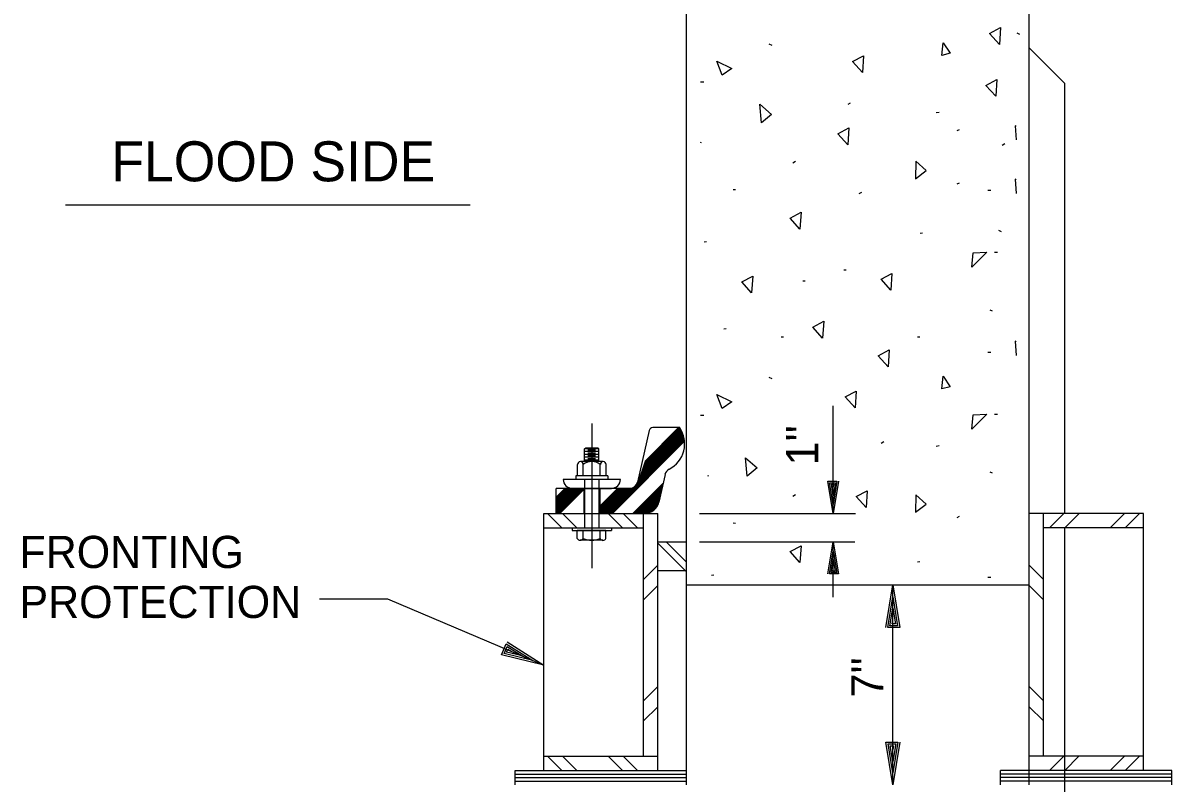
# Model space of a CAD drawing. Extents: x 22369.6 to 22389.4, y 22369.6 to 22386.
# Drawn here: x 22376.745 to 22378.422, y 22378.617 to 22379.725 of the extents above; entities that cross this region are included whole.
import ezdxf

# ---------------------------------------------------------------- set-up
doc = ezdxf.new("R2010")
doc.units = 0
for name, color, linetype in [('Level 1', 7, 'Continuous'), ('Level 10', 7, 'Continuous'), ('Level 2', 7, 'Continuous'), ('Level 3', 7, 'Continuous'), ('Level 4', 7, 'Continuous'), ('Level 44', 7, 'Continuous'), ('Level 7', 7, 'Continuous')]:
    doc.layers.add(name, color=color, linetype=linetype)

msp = doc.modelspace()

# ---------------------------------------------------------------- linework, layer by layer
at = {"layer": 'Level 1'}
for p, q in [((22377.9274, 22379.0098), (22377.9274, 22379.1666)), ((22377.5753, 22379.1407), (22377.5753, 22378.93)), ((22377.7095, 22379.1213), (22377.6416, 22379.0534)), ((22377.7093, 22379.122), (22377.6421, 22379.0548)), ((22377.7091, 22379.1227), (22377.6426, 22379.0562)), ((22377.7089, 22379.1234), (22377.6431, 22379.0577)), ((22377.7087, 22379.1242), (22377.6436, 22379.0591)), ((22377.7084, 22379.1248), (22377.6441, 22379.0605)), ((22377.7082, 22379.1255), (22377.6446, 22379.0619)), ((22377.708, 22379.1262), (22377.6451, 22379.0634)), ((22377.7077, 22379.1269), (22377.6456, 22379.0648)), ((22377.7074, 22379.1275), (22377.6461, 22379.0662)), ((22377.7071, 22379.1282), (22377.6466, 22379.0676)), ((22377.7069, 22379.1288), (22377.6471, 22379.069)), ((22377.7066, 22379.1294), (22377.6476, 22379.0705)), ((22377.7063, 22379.13), (22377.6481, 22379.0719)), ((22377.706, 22379.1306), (22377.6486, 22379.0733)), ((22377.7056, 22379.1312), (22377.6491, 22379.0747)), ((22377.7053, 22379.1318), (22377.6496, 22379.0762)), ((22377.705, 22379.1324), (22377.6501, 22379.0776)), ((22377.7046, 22379.133), (22377.6506, 22379.079)), ((22377.7043, 22379.1336), (22377.6511, 22379.0804)), ((22377.7039, 22379.1341), (22377.6516, 22379.0819)), ((22377.7035, 22379.1347), (22377.6521, 22379.0833)), ((22377.7027, 22379.1348), (22377.6526, 22379.0847)), ((22377.7018, 22379.1348), (22377.6531, 22379.0861)), ((22377.5648, 22379.104), (22377.5659, 22379.1051)), ((22377.5846, 22379.1051), (22377.5659, 22379.1051)), ((22377.5857, 22379.104), (22377.5846, 22379.1051)), ((22377.7098, 22379.12), (22377.5996, 22379.0098)), ((22377.7099, 22379.1194), (22377.6003, 22379.0098)), ((22377.71, 22379.1188), (22377.601, 22379.0098)), ((22377.7101, 22379.1182), (22377.6017, 22379.0098)), ((22377.7102, 22379.1176), (22377.6024, 22379.0098)), ((22377.7103, 22379.1169), (22377.6031, 22379.0098)), ((22377.7104, 22379.1163), (22377.6038, 22379.0098)), ((22377.7105, 22379.1157), (22377.6046, 22379.0098)), ((22377.7105, 22379.115), (22377.6053, 22379.0098)), ((22377.7097, 22379.1205), (22377.6404, 22379.0513)), ((22377.5857, 22379.1041), (22377.5648, 22379.1041)), ((22377.5648, 22379.0853), (22377.5648, 22379.104)), ((22377.5857, 22379.0999), (22377.5648, 22379.0999)), ((22377.5857, 22379.0957), (22377.5648, 22379.0957)), ((22377.5857, 22379.0916), (22377.5648, 22379.0916)), ((22377.5805, 22379.102), (22377.5695, 22379.102)), ((22377.5805, 22379.0978), (22377.5695, 22379.0978)), ((22377.5805, 22379.0936), (22377.5695, 22379.0936)), ((22377.5805, 22379.0895), (22377.5695, 22379.0895)), ((22377.5857, 22379.0853), (22377.5857, 22379.104)), ((22377.5544, 22379.0645), (22377.5544, 22379.0811)), ((22377.5544, 22379.0811), (22377.5544, 22379.0811)), ((22377.5918, 22379.0853), (22377.5586, 22379.0853)), ((22377.5628, 22379.0645), (22377.5628, 22379.0811)), ((22377.5857, 22379.0874), (22377.5648, 22379.0874)), ((22377.5875, 22379.0645), (22377.5875, 22379.0811)), ((22377.5961, 22379.0645), (22377.5961, 22379.0811)), ((22377.5987, 22379.0645), (22377.5518, 22379.0645)), ((22377.5518, 22379.0645), (22377.5518, 22379.0593)), ((22377.5648, 22379.0593), (22377.5648, 22378.9889)), ((22377.5857, 22379.0593), (22377.5857, 22378.9889)), ((22377.5987, 22379.0645), (22377.5987, 22379.0593)), ((22377.5593, 22379.0462), (22377.5232, 22379.0101)), ((22377.5586, 22379.0462), (22377.5232, 22379.0108)), ((22377.5579, 22379.0462), (22377.5232, 22379.0115)), ((22377.5572, 22379.0462), (22377.5232, 22379.0122)), ((22377.5565, 22379.0462), (22377.5232, 22379.0129)), ((22377.5558, 22379.0462), (22377.5232, 22379.0136)), ((22377.5551, 22379.0462), (22377.5232, 22379.0143)), ((22377.5544, 22379.0462), (22377.5232, 22379.015)), ((22377.5537, 22379.0462), (22377.5232, 22379.0158)), ((22377.553, 22379.0462), (22377.5232, 22379.0165)), ((22377.5522, 22379.0462), (22377.5232, 22379.0172)), ((22377.5515, 22379.0462), (22377.5232, 22379.0179)), ((22377.5508, 22379.0462), (22377.5232, 22379.0186)), ((22377.5501, 22379.0462), (22377.5232, 22379.0193)), ((22377.5494, 22379.0462), (22377.5232, 22379.02)), ((22377.5487, 22379.0462), (22377.5232, 22379.0207)), ((22377.548, 22379.0462), (22377.5232, 22379.0214)), ((22377.5473, 22379.0462), (22377.5232, 22379.0221)), ((22377.5466, 22379.0462), (22377.5232, 22379.0228)), ((22377.5459, 22379.0462), (22377.5232, 22379.0235)), ((22377.5452, 22379.0462), (22377.5232, 22379.0243)), ((22377.5445, 22379.0462), (22377.5232, 22379.0249)), ((22377.5438, 22379.0462), (22377.5232, 22379.0257)), ((22377.5431, 22379.0462), (22377.5232, 22379.0264)), ((22377.5423, 22379.0462), (22377.5232, 22379.0271)), ((22377.5416, 22379.0462), (22377.5232, 22379.0278)), ((22377.5409, 22379.0462), (22377.5232, 22379.0285)), ((22377.5402, 22379.0462), (22377.5232, 22379.0292)), ((22377.5395, 22379.0462), (22377.5232, 22379.0299)), ((22377.5388, 22379.0462), (22377.5232, 22379.0306)), ((22377.5381, 22379.0462), (22377.5232, 22379.0313)), ((22377.5374, 22379.0462), (22377.5232, 22379.032)), ((22377.5367, 22379.0462), (22377.5232, 22379.0327)), ((22377.536, 22379.0462), (22377.5232, 22379.0334)), ((22377.56, 22379.0462), (22377.5236, 22379.0098)), ((22377.5607, 22379.0462), (22377.5243, 22379.0098)), ((22377.5615, 22379.0462), (22377.525, 22379.0098)), ((22377.5622, 22379.0462), (22377.5257, 22379.0098)), ((22377.5628, 22379.0462), (22377.5264, 22379.0098)), ((22377.5636, 22379.0462), (22377.5271, 22379.0098)), ((22377.5636, 22379.0455), (22377.5278, 22379.0098)), ((22377.5636, 22379.0448), (22377.5285, 22379.0098)), ((22377.5636, 22379.0448), (22377.5286, 22379.0098)), ((22377.6233, 22379.0462), (22377.5869, 22379.0098)), ((22377.6226, 22379.0462), (22377.587, 22379.0106)), ((22377.6219, 22379.0462), (22377.587, 22379.0113)), ((22377.6212, 22379.0462), (22377.587, 22379.012)), ((22377.6205, 22379.0462), (22377.587, 22379.0127)), ((22377.6198, 22379.0462), (22377.587, 22379.0134)), ((22377.6191, 22379.0462), (22377.587, 22379.0141)), ((22377.6184, 22379.0462), (22377.587, 22379.0148)), ((22377.6177, 22379.0462), (22377.587, 22379.0155)), ((22377.617, 22379.0462), (22377.587, 22379.0163)), ((22377.6163, 22379.0462), (22377.587, 22379.017)), ((22377.6156, 22379.0462), (22377.587, 22379.0177)), ((22377.6149, 22379.0462), (22377.587, 22379.0184)), ((22377.6141, 22379.0462), (22377.587, 22379.0191)), ((22377.6134, 22379.0462), (22377.587, 22379.0198)), ((22377.6127, 22379.0462), (22377.587, 22379.0205)), ((22377.624, 22379.0462), (22377.5876, 22379.0098)), ((22377.6248, 22379.0462), (22377.5883, 22379.0098)), ((22377.6255, 22379.0462), (22377.589, 22379.0098)), ((22377.6262, 22379.0462), (22377.5897, 22379.0098)), ((22377.6269, 22379.0462), (22377.5904, 22379.0098)), ((22377.6276, 22379.0462), (22377.5911, 22379.0098)), ((22377.6283, 22379.0462), (22377.5918, 22379.0098)), ((22377.629, 22379.0462), (22377.5925, 22379.0098)), ((22377.6297, 22379.0462), (22377.5932, 22379.0098)), ((22377.6304, 22379.0462), (22377.594, 22379.0098)), ((22377.6311, 22379.0462), (22377.5947, 22379.0098)), ((22377.6318, 22379.0462), (22377.5954, 22379.0098)), ((22377.6325, 22379.0462), (22377.5961, 22379.0098)), ((22377.6336, 22379.0466), (22377.5968, 22379.0098)), ((22377.6346, 22379.0469), (22377.5975, 22379.0098)), ((22377.6358, 22379.0474), (22377.5982, 22379.0098)), ((22377.6374, 22379.0483), (22377.5989, 22379.0098)), ((22377.6352, 22379.0098), (22377.6791, 22379.0537)), ((22377.6359, 22379.0098), (22377.6789, 22379.0528)), ((22377.6366, 22379.0098), (22377.6787, 22379.0519)), ((22377.6373, 22379.0098), (22377.6785, 22379.051)), ((22377.638, 22379.0098), (22377.6783, 22379.0501)), ((22377.6387, 22379.0098), (22377.6781, 22379.0492)), ((22377.6394, 22379.0098), (22377.6779, 22379.0483)), ((22377.6401, 22379.0098), (22377.6777, 22379.0474)), ((22377.6408, 22379.0098), (22377.6775, 22379.0464)), ((22377.6415, 22379.0098), (22377.6773, 22379.0455)), ((22377.6422, 22379.0098), (22377.6771, 22379.0446)), ((22377.643, 22379.0098), (22377.6769, 22379.0437)), ((22377.6437, 22379.0098), (22377.6764, 22379.0426)), ((22377.6444, 22379.0098), (22377.6765, 22379.0419)), ((22377.6451, 22379.0098), (22377.6763, 22379.041)), ((22377.6458, 22379.0098), (22377.6761, 22379.0401)), ((22377.6465, 22379.0098), (22377.6759, 22379.0392)), ((22377.6472, 22379.0098), (22377.6757, 22379.0383)), ((22377.6479, 22379.0098), (22377.6755, 22379.0373)), ((22377.6752, 22379.0364), (22377.6486, 22379.0098)), ((22377.675, 22379.0355), (22377.6493, 22379.0098)), ((22377.6748, 22379.0346), (22377.65, 22379.0098)), ((22377.6746, 22379.0337), (22377.6507, 22379.0098)), ((22377.6744, 22379.0328), (22377.6514, 22379.0098)), ((22377.6742, 22379.0319), (22377.6522, 22379.0099)), ((22377.674, 22379.031), (22377.6528, 22379.0098)), ((22377.6738, 22379.0301), (22377.6536, 22379.0098)), ((22377.6736, 22379.0292), (22377.6543, 22379.0099)), ((22377.6734, 22379.0282), (22377.6551, 22379.0099)), ((22377.6732, 22379.0273), (22377.656, 22379.01)), ((22377.673, 22379.0264), (22377.6568, 22379.0102)), ((22377.6728, 22379.0255), (22377.6577, 22379.0104)), ((22377.6725, 22379.0245), (22377.6587, 22379.0107)), ((22377.6722, 22379.0234), (22377.6598, 22379.0111)), ((22377.6715, 22379.0219), (22377.6613, 22379.0117)), ((22377.5314, 22378.9889), (22377.5106, 22379.0098)), ((22377.5535, 22378.9889), (22377.5327, 22379.0098)), ((22377.6198, 22378.9889), (22377.599, 22379.0098)), ((22377.6419, 22378.9889), (22377.6211, 22379.0098)), ((22377.6705, 22379.0199), (22377.6633, 22379.0127)), ((22377.7321, 22379.0098), (22377.96, 22379.0098)), ((22378.243, 22378.9889), (22378.2639, 22379.0098)), ((22378.2651, 22378.9889), (22378.286, 22379.0098)), ((22378.3314, 22378.9889), (22378.3522, 22379.0098)), ((22378.3535, 22378.9889), (22378.3743, 22379.0098)), ((22377.5466, 22378.9889), (22377.5466, 22378.985)), ((22377.6039, 22378.9889), (22377.6039, 22378.985)), ((22377.5466, 22378.985), (22377.6039, 22378.985)), ((22377.5958, 22378.985), (22377.5541, 22378.985)), ((22377.5541, 22378.9733), (22377.5541, 22378.985)), ((22377.5915, 22378.9705), (22377.5583, 22378.9705)), ((22377.5625, 22378.9732), (22377.5625, 22378.985)), ((22377.5872, 22378.9732), (22377.5872, 22378.985)), ((22377.5958, 22378.9733), (22377.5958, 22378.985)), ((22377.7133, 22378.9247), (22377.6716, 22378.9664)), ((22377.7133, 22378.9384), (22377.6836, 22378.9681)), ((22377.7321, 22378.9681), (22377.9591, 22378.9681)), ((22377.9274, 22378.8878), (22377.9274, 22378.9681)), ((22377.6508, 22378.9132), (22377.6716, 22378.9341)), ((22378.2341, 22378.9132), (22378.2133, 22378.9341)), ((22377.6508, 22378.8838), (22377.6716, 22378.9046)), ((22378.0144, 22378.6139), (22378.0144, 22378.9056)), ((22378.2341, 22378.8838), (22378.2133, 22378.9046)), ((22377.6508, 22378.7365), (22377.6716, 22378.7573)), ((22378.2341, 22378.7365), (22378.2133, 22378.7573)), ((22377.6508, 22378.707), (22377.6716, 22378.7278)), ((22378.2341, 22378.707), (22378.2133, 22378.7278)), ((22377.5314, 22378.6348), (22377.5106, 22378.6556)), ((22377.5535, 22378.6348), (22377.5327, 22378.6556)), ((22377.6198, 22378.6348), (22377.599, 22378.6556)), ((22377.6419, 22378.6348), (22377.6211, 22378.6556)), ((22378.2431, 22378.6348), (22378.2639, 22378.6556)), ((22378.2651, 22378.6348), (22378.2859, 22378.6556)), ((22378.3314, 22378.6348), (22378.3522, 22378.6556)), ((22378.3535, 22378.6348), (22378.3743, 22378.6556)), ((22377.4633, 22378.6296), (22377.7133, 22378.6296)), ((22377.4633, 22378.6244), (22377.7133, 22378.6244)), ((22377.4633, 22378.6192), (22377.7133, 22378.6192)), ((22378.4216, 22378.6296), (22378.1716, 22378.6296)), ((22378.4216, 22378.6244), (22378.1716, 22378.6244)), ((22378.4216, 22378.6192), (22378.1716, 22378.6192))]:
    msp.add_line(p, q, dxfattribs=at)
for centre, radius, start, end in [((22377.5586, 22379.081), 0.00421, 0.4975, 179.5025), ((22377.5752, 22379.065), 0.0203, 52.4343, 127.5657), ((22377.5919, 22379.081), 0.00422, 0.5659, 179.4342), ((22377.5583, 22378.9751), 0.00456, 202.8005, 337.625), ((22377.575, 22378.9989), 0.0285, 244.116, 295.4481), ((22377.5915, 22378.9751), 0.00469, 204.0009, 336.8325)]:
    msp.add_arc(centre, radius, start, end, dxfattribs=at)
at = {"layer": 'Level 10'}
msp.add_line((22377.398, 22379.4593), (22376.8073, 22379.4593), dxfattribs=at)
at = {"layer": 'Level 2'}
for p, q in [((22377.659, 22379.1307), (22377.6421, 22379.0554)), ((22377.7035, 22379.1348), (22377.6641, 22379.1348)), ((22377.6169, 22379.0593), (22377.5336, 22379.0593)), ((22377.682, 22379.0664), (22377.6729, 22379.0261)), ((22377.6307, 22379.0462), (22377.5232, 22379.0462)), ((22377.5232, 22379.0098), (22377.5232, 22379.0462)), ((22377.5466, 22379.0462), (22377.6039, 22379.0462)), ((22377.5636, 22379.0462), (22377.5636, 22379.0098)), ((22377.587, 22379.0462), (22377.587, 22379.0098)), ((22377.9274, 22379.0228), (22377.9274, 22379.0228)), ((22377.505, 22379.0098), (22377.6716, 22379.0098)), ((22377.505, 22378.6348), (22377.505, 22379.0098)), ((22377.5232, 22379.0098), (22377.6526, 22379.0098)), ((22377.6508, 22378.6556), (22377.6508, 22379.0098)), ((22377.6716, 22378.6348), (22377.6716, 22379.0098)), ((22377.9274, 22379.0098), (22377.9274, 22379.0098)), ((22378.38, 22379.0098), (22378.2133, 22379.0098)), ((22378.2133, 22378.6348), (22378.2133, 22379.0098)), ((22378.2341, 22378.6556), (22378.2341, 22379.0098)), ((22378.38, 22378.6348), (22378.38, 22379.0098)), ((22377.505, 22378.9889), (22377.6508, 22378.9889)), ((22378.38, 22378.9889), (22378.2341, 22378.9889)), ((22377.6716, 22378.9681), (22377.7133, 22378.9681)), ((22377.7133, 22378.6139), (22377.7133, 22378.9681)), ((22377.9274, 22378.9681), (22377.9274, 22378.9681)), ((22377.9274, 22378.9551), (22377.9274, 22378.9551)), ((22377.6716, 22378.9264), (22377.7133, 22378.9264)), ((22378.0144, 22378.9056), (22378.0144, 22378.9056)), ((22378.0144, 22378.8883), (22378.0144, 22378.8883)), ((22377.489, 22378.7953), (22377.489, 22378.7953)), ((22377.505, 22378.7886), (22377.505, 22378.7886)), ((22377.505, 22378.6556), (22377.6716, 22378.6556)), ((22378.38, 22378.6556), (22378.2133, 22378.6556)), ((22377.4633, 22378.6348), (22377.7133, 22378.6348)), ((22377.4633, 22378.6139), (22377.4633, 22378.6348)), ((22378.0144, 22378.6313), (22378.0144, 22378.6313)), ((22378.4216, 22378.6348), (22378.1716, 22378.6348)), ((22378.1716, 22378.6139), (22378.1716, 22378.6348)), ((22378.4216, 22378.6139), (22378.4216, 22378.6348))]:
    msp.add_line(p, q, dxfattribs=at)
for points in [[(22377.9352, 22379.0565), (22377.9274, 22379.0098), (22377.9197, 22379.0565), (22377.9329, 22379.0565), (22377.9274, 22379.0228), (22377.9222, 22379.0545), (22377.9307, 22379.0545), (22377.9274, 22379.0353), (22377.9247, 22379.0525), (22377.9282, 22379.0525), (22377.9274, 22379.0483)], [(22377.9197, 22378.9214), (22377.9274, 22378.9681), (22377.9352, 22378.9214), (22377.9219, 22378.9214), (22377.9274, 22378.9551), (22377.9327, 22378.9234), (22377.9242, 22378.9234), (22377.9274, 22378.9426), (22377.9302, 22378.9254), (22377.9267, 22378.9254), (22377.9274, 22378.9296)], [(22378.0041, 22378.8433), (22378.0144, 22378.9056), (22378.0247, 22378.8433), (22378.0071, 22378.8433), (22378.0144, 22378.8883), (22378.0214, 22378.8459), (22378.0101, 22378.8459), (22378.0144, 22378.8716), (22378.0181, 22378.8486), (22378.0134, 22378.8486), (22378.0144, 22378.8543)], [(22377.1781, 22378.8851), (22377.2771, 22378.8851), (22377.505, 22378.7886)], [(22377.4516, 22378.8224), (22377.505, 22378.7886), (22377.4435, 22378.8034), (22377.4504, 22378.8196), (22377.489, 22378.7953), (22377.4473, 22378.8054), (22377.4517, 22378.8158), (22377.4736, 22378.8018), (22377.451, 22378.8074), (22377.4529, 22378.8117), (22377.4577, 22378.8086)], [(22378.0247, 22378.6763), (22378.0144, 22378.6139), (22378.0041, 22378.6763), (22378.0217, 22378.6763), (22378.0144, 22378.6313), (22378.0074, 22378.6736), (22378.0187, 22378.6736), (22378.0144, 22378.6479), (22378.0107, 22378.6709), (22378.0154, 22378.6709), (22378.0144, 22378.6653)]]:
    msp.add_lwpolyline(points, dxfattribs=at)
for centre, radius, start, end in [((22377.6641, 22379.1296), 0.00521, 90, 167.3821), ((22377.669, 22379.1113), 0.0417, 297.1705, 34.2289), ((22377.6934, 22379.0639), 0.0117, 117.1705, 167.3835), ((22377.5466, 22379.0593), 0.013, 180, 270), ((22377.6039, 22379.0593), 0.013, 270, 0), ((22377.6307, 22379.058), 0.0117, 270, 347.3806), ((22377.6526, 22379.0306), 0.0208, 270, 347.3827)]:
    msp.add_arc(centre, radius, start, end, dxfattribs=at)
at = {"layer": 'Level 3'}
msp.add_line((22377.7133, 22379.4071), (22377.7133, 22379.4139), dxfattribs=at)
at = {"layer": 'Level 44'}
for p, q in [((22378.1953, 22379.7108), (22378.1993, 22379.7088)), ((22377.8336, 22379.6946), (22377.8376, 22379.6926)), ((22377.734, 22379.6393), (22377.7385, 22379.6393)), ((22377.949, 22379.6064), (22377.9528, 22379.6087)), ((22378.0778, 22379.5943), (22378.0821, 22379.595)), ((22378.108, 22379.5681), (22378.1115, 22379.5698)), ((22377.7334, 22379.5512), (22377.7349, 22379.5508)), ((22378.174, 22379.5469), (22378.1778, 22379.5491)), ((22377.8687, 22379.5212), (22377.8725, 22379.5234)), ((22378.108, 22379.4902), (22378.1115, 22379.4919)), ((22377.7814, 22379.4822), (22377.785, 22379.4819)), ((22377.9651, 22379.4761), (22377.9689, 22379.4784)), ((22378.153, 22379.481), (22378.1575, 22379.481)), ((22378.1683, 22379.423), (22378.1723, 22379.421)), ((22377.7393, 22379.4059), (22377.7426, 22379.4065)), ((22378.0543, 22379.4185), (22378.0577, 22379.4187)), ((22378.1626, 22379.3909), (22378.1669, 22379.3909)), ((22377.9429, 22379.3647), (22377.9462, 22379.3649)), ((22377.8832, 22379.3488), (22377.8865, 22379.349)), ((22378.156, 22379.3065), (22378.1593, 22379.3053)), ((22377.7678, 22379.2791), (22377.7711, 22379.2793)), ((22377.8514, 22379.2671), (22377.8547, 22379.2674)), ((22378.0504, 22379.2671), (22378.0537, 22379.2674)), ((22378.153, 22379.2448), (22378.1575, 22379.2448)), ((22377.8336, 22379.2084), (22377.8376, 22379.2064)), ((22377.734, 22379.153), (22377.7385, 22379.153)), ((22378.1626, 22379.1546), (22378.1669, 22379.1546)), ((22377.9973, 22379.1123), (22378.001, 22379.1145)), ((22378.0778, 22379.108), (22378.0821, 22379.1088)), ((22377.7438, 22379.0649), (22377.7453, 22379.0645)), ((22378.156, 22379.0703), (22378.1593, 22379.069)), ((22377.8687, 22379.0349), (22377.8725, 22379.0372)), ((22378.108, 22379.0039), (22378.1115, 22379.0056)), ((22377.7814, 22378.9959), (22377.785, 22378.9956)), ((22377.9276, 22378.9469), (22377.9314, 22378.9491)), ((22378.0504, 22378.9392), (22378.0537, 22378.9394)), ((22377.7497, 22378.9197), (22377.753, 22378.9203)), ((22378.153, 22378.9169), (22378.1575, 22378.9169))]:
    msp.add_line(p, q, dxfattribs=at)
for points in [[(22378.1698, 22379.6937), (22378.1555, 22379.7097), (22378.1714, 22379.7182)], [(22378.0856, 22379.6777), (22378.088, 22379.6959), (22378.0982, 22379.6807)], [(22377.97, 22379.6527), (22377.9557, 22379.6687), (22377.9716, 22379.6772)], [(22377.7655, 22379.649), (22377.7575, 22379.6694), (22377.7796, 22379.6587)], [(22378.1644, 22379.618), (22378.1501, 22379.634), (22378.166, 22379.6425)], [(22377.8201, 22379.6063), (22377.8372, 22379.5914), (22377.823, 22379.5794)], [(22377.9485, 22379.5474), (22377.9343, 22379.5634), (22377.9502, 22379.5719)], [(22378.0472, 22379.4976), (22378.0632, 22379.5097), (22378.0479, 22379.5233)], [(22377.8789, 22379.4243), (22377.8646, 22379.4403), (22377.8805, 22379.4488)], [(22378.1314, 22379.3898), (22378.1514, 22379.3909), (22378.1297, 22379.3687)], [(22378.0114, 22379.3352), (22377.9972, 22379.3512), (22378.0131, 22379.3597)], [(22377.8084, 22379.3312), (22377.7942, 22379.3472), (22377.8101, 22379.3557)], [(22377.9119, 22379.2655), (22377.8977, 22379.2815), (22377.9136, 22379.29)], [(22378.0075, 22379.2237), (22377.9932, 22379.2397), (22378.0091, 22379.2482)], [(22378.0856, 22379.1914), (22378.088, 22379.2097), (22378.0982, 22379.1944)], [(22377.7655, 22379.1628), (22377.7575, 22379.1832), (22377.7796, 22379.1724)], [(22377.9592, 22379.1636), (22377.945, 22379.1796), (22377.9609, 22379.1881)], [(22378.1314, 22379.1535), (22378.1514, 22379.1546), (22378.1297, 22379.1324)], [(22377.7992, 22379.091), (22377.8163, 22379.0761), (22377.8021, 22379.0642)], [(22377.9753, 22379.0182), (22377.961, 22379.0342), (22377.977, 22379.0427)], [(22378.0472, 22379.0114), (22378.0632, 22379.0234), (22378.0479, 22379.037)], [(22377.8789, 22378.938), (22377.8646, 22378.954), (22377.8805, 22378.9625)]]:
    msp.add_lwpolyline(points, close=True, dxfattribs=at)
for points in [[(22378.1941, 22379.5739), (22378.193, 22379.5749), (22378.1941, 22379.5543)], [(22378.1941, 22379.496), (22378.193, 22379.497), (22378.1941, 22379.4764)], [(22378.1941, 22379.2598), (22378.193, 22379.2608), (22378.1941, 22379.2401)]]:
    msp.add_lwpolyline(points, dxfattribs=at)
at = {"layer": 'Level 7'}
for p, q in [((22377.7133, 22378.6139), (22377.7133, 22380.0223)), ((22378.2133, 22378.6139), (22378.2133, 22380.0223)), ((22378.2133, 22379.6889), (22378.2654, 22379.6369)), ((22378.2654, 22379.0098), (22378.2654, 22379.6369)), ((22378.2654, 22377.6556), (22378.2654, 22378.9889)), ((22377.7133, 22378.9056), (22378.2133, 22378.9056))]:
    msp.add_line(p, q, dxfattribs=at)

# ---------------------------------------------------------------- texts
at = {"layer": 'Level 10'}
msp.add_text('FLOOD SIDE', height=0.05833, dxfattribs=at).set_placement((22376.8743, 22379.494))
at = {"layer": 'Level 4'}
for s, p in [("1''", (22377.9055, 22379.0797)), ("7''", (22378.0005, 22378.7413))]:
    msp.add_text(s, height=0.04688, rotation=90, dxfattribs=at).set_placement(p)
for s, p in [('FRONTING', (22376.7403, 22378.9301)), ('PROTECTION', (22376.7403, 22378.8572))]:
    msp.add_text(s, height=0.04688, dxfattribs=at).set_placement(p)

doc.saveas('drawing.dxf')
